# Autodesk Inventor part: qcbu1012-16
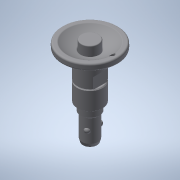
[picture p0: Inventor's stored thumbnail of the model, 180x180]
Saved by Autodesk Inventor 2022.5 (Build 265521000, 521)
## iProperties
Created: 2016-12
Part Number: qcbu1012-16
Material: 一般
Document SubType Name: Modeling
Designer: imaocorp
Density: 1 g/cm^3
Appearance: 既定
Author: imaocorp
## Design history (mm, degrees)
node "qcbu1012-16.x_t1"
node "E形止メ輪 呼ビ3 ステンレス"
node "Base1"
